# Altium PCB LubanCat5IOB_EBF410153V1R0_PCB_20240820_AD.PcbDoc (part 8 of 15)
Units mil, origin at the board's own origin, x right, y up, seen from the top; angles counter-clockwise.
Board outline 6811.02 x 4055.12 mil, 6 copper layers (TOP, GND02, ART03, ART04, PWR05, BOTTOM), stack 59.279 mil thick; 981 components, 783 nets, 3627 pads, 2669 vias.
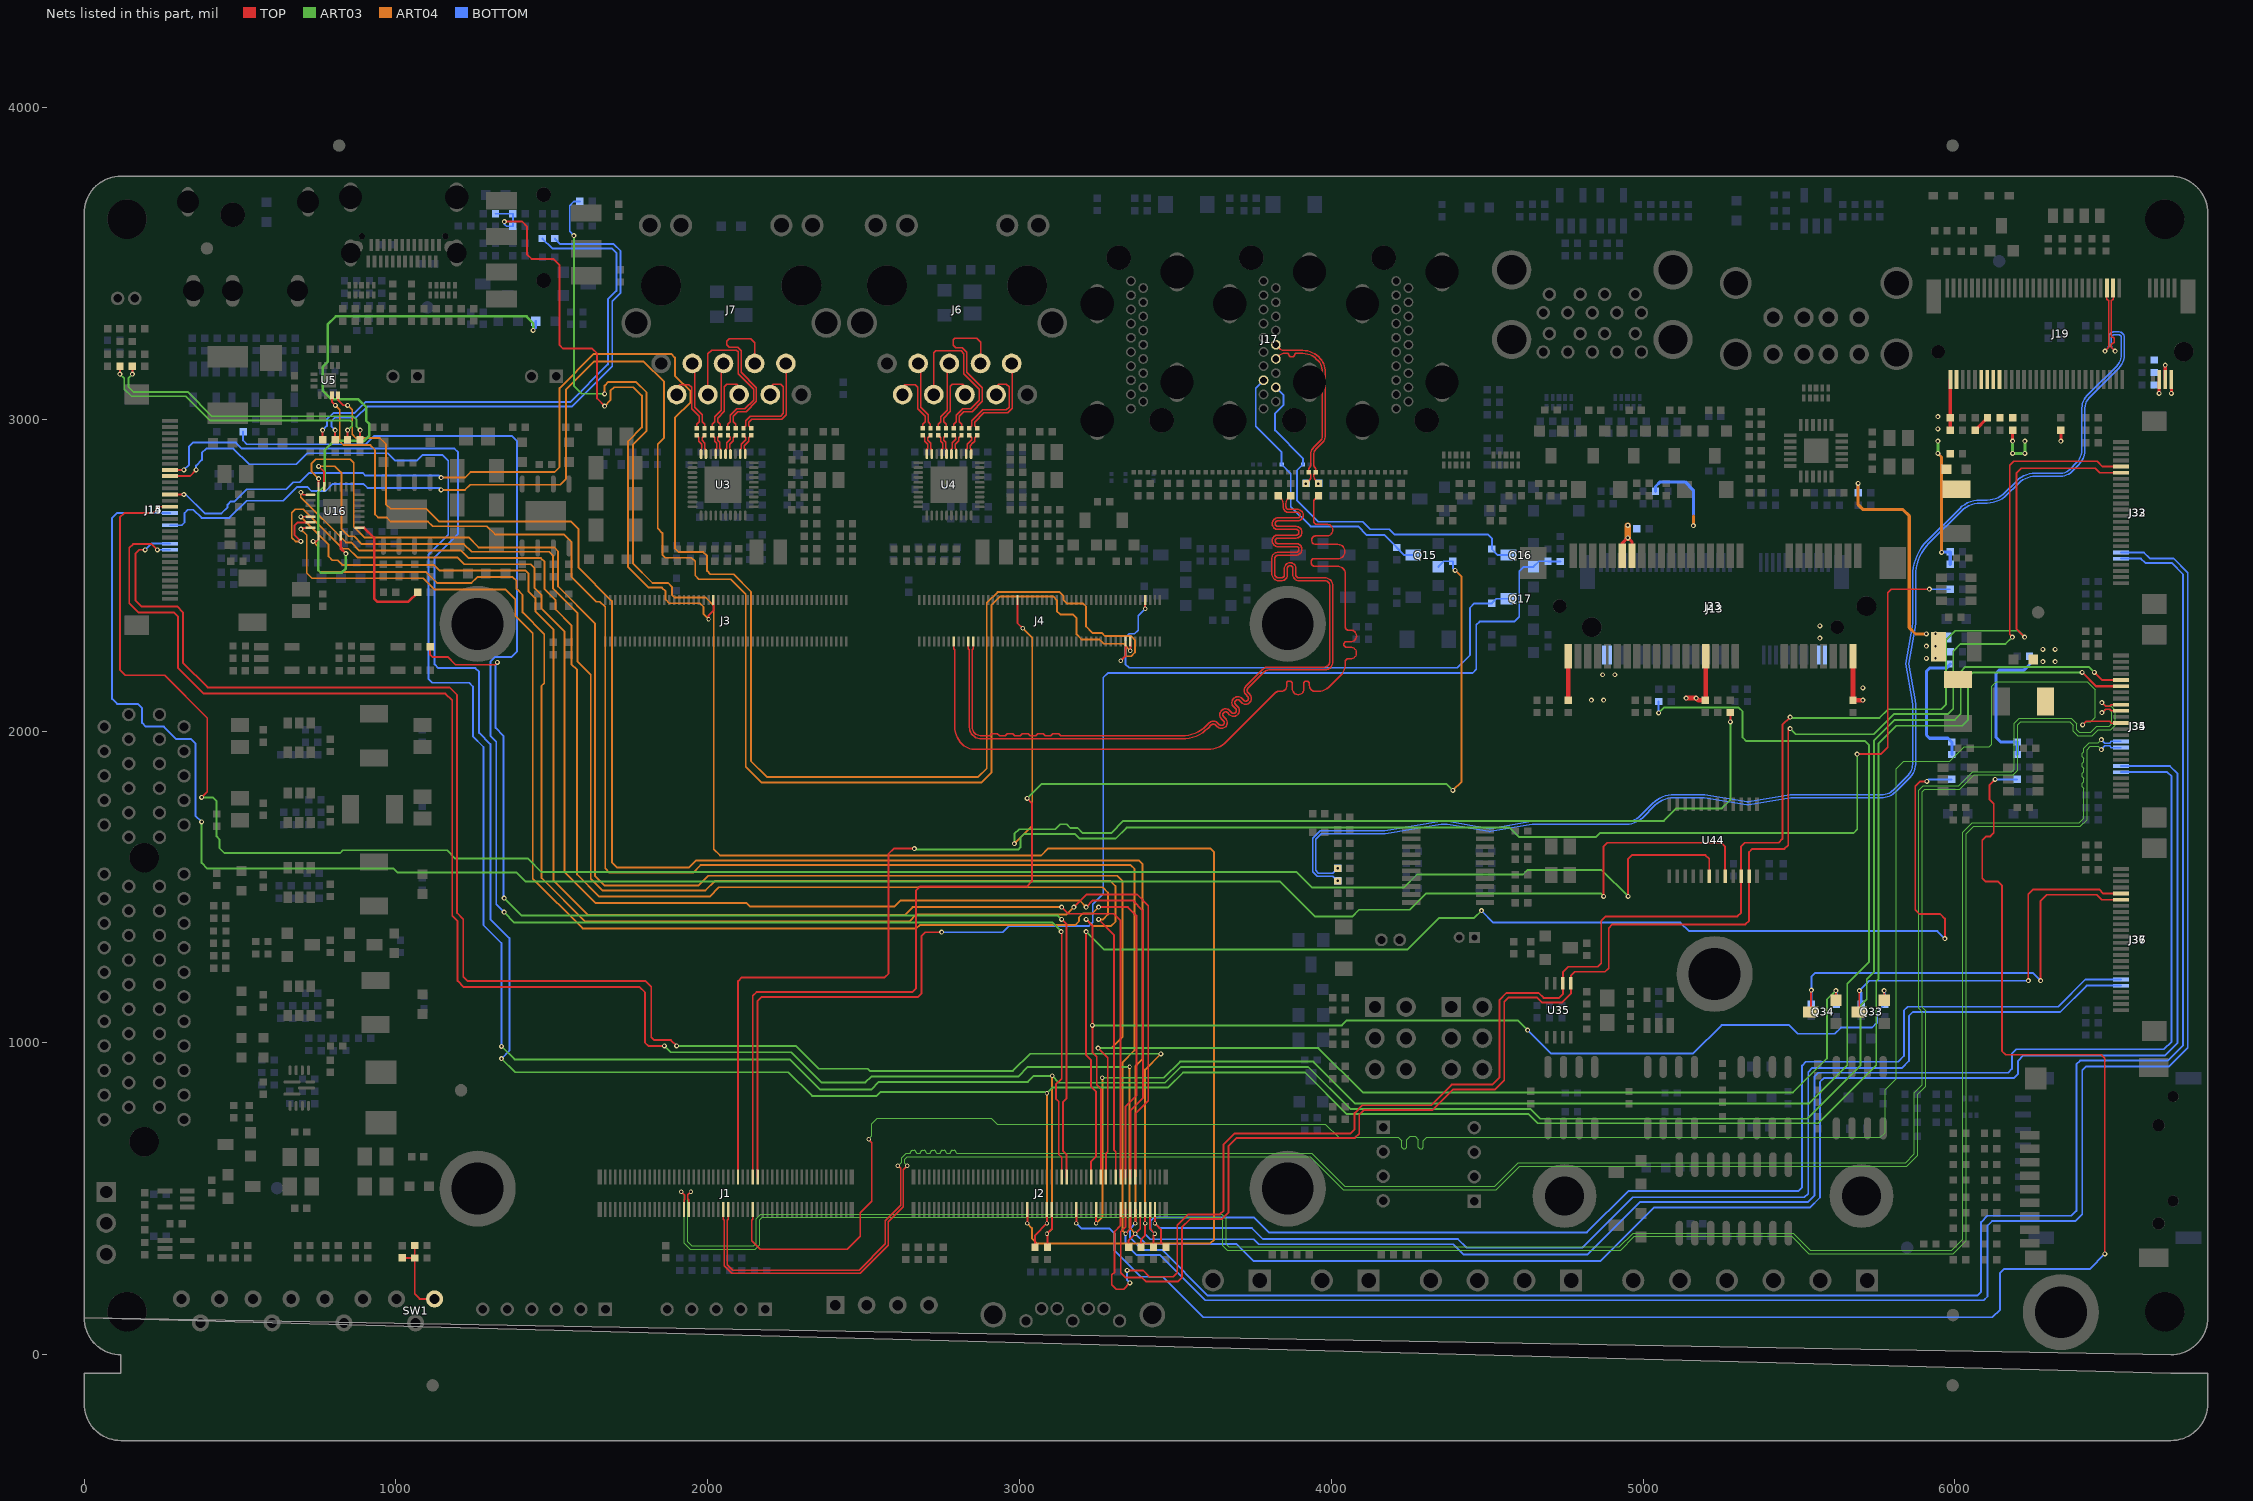
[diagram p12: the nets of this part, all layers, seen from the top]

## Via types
v1: diameter 16, hole 8, TOP to BOTTOM, 2357 vias
v2: diameter 14, hole 8, TOP to BOTTOM, 308 vias
v3: diameter 20, hole 10, TOP to BOTTOM, 4 vias

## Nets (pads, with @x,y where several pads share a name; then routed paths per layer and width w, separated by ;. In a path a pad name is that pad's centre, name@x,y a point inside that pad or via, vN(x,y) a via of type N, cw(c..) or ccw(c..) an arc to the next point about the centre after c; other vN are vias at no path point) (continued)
HDMI_TX1_D3N_PORT: C150.2 D66.2 J17.12 R182.1 | length 581.9
  TOP w4.5: J17.12@3822.28,3193.52 3833.7,3204.93 cw(c3849.61,3189.02) 3849.61,3211.52 3859.11,3211.52 cw(c3859.11,3206.26) 3864.37,3206.26 ccw(c3869.63,3206.26) 3869.63,3201 3877.11,3201 ccw(c3877.11,3206.26) 3882.37,3206.26 cw(c3887.63,3206.26) 3887.63,3211.52 3908.7,3211.52 cw(c3908.7,3149.46) 3952.59,3193.34 3958.25,3187.69 cw(c3928.67,3158.11) 3970.5,3158.11 3970.5,2942.32 cw(c3957.5,2942.32) 3966.69,2933.13 3943.76,2910.2 ccw(c3966.73,2887.23) 3934.25,2887.23 3934.25,2853.33 cw(c3924.38,2853.33) 3931.36,2846.35 3930.72,2845.71 ccw(c3937.7,2838.73) 3927.83,2838.73 D66.2@3927.83,2830 3931.73,2826.1 cw(c3923.85,2818.21) 3935,2818.21 3935,2815.99 cw(c3920.66,2815.99) 3930.8,2805.85 v1(3919,2794.05)
HDMI_TX1_D3P: C149.1 J4.15 | length 2829.7
  TOP w4.5: J4.15@2788.99,2286.88 2788.99,2263.82 2792.11,2260.7 2792.11,2015.33 ccw(c2872.84,2015.33) 2815.76,1958.25 ccw(c2854.97,1997.45) 2854.97,1942 3604.78,1942 ccw(c3604.77,2027.04) 3664.91,1966.91 3822.36,2124.36 cw(c3828.73,2118) 3828.73,2127 3838.7,2127 ccw(c3838.7,2145.5) 3857.2,2145.5 3857.2,2153.25 cw(c3864.45,2153.25) 3864.45,2160.5 3866.2,2160.5 cw(c3866.2,2151.5) 3875.2,2151.5 3875.2,2135.5 ccw(c3893.7,2135.5) 3912.2,2135.5 3912.2,2153.25 cw(c3919.45,2153.25) 3919.45,2160.5 3921.2,2160.5 cw(c3921.2,2151.5) 3930.2,2151.5 3930.2,2145.5 ccw(c3948.7,2145.5) 3948.7,2127 3958.2,2127 ccw(c3958.2,2174.79) 3992,2141 4030.69,2179.69 ccw(c3994.93,2215.45) 4045.5,2215.45 4045.5,2223.68 cw(c4053.74,2223.68) 4053.73,2231.91 4062.5,2231.91 ccw(c4062.5,2250.41) 4062.5,2268.91 4049.5,2268.91 cw(c4049.5,2277.91) 4049.5,2286.91 4063.25,2286.91 ccw(c4063.25,2304.66) 4081,2304.66 4081,2305.41 ccw(c4062.5,2305.41) 4062.5,2323.91 4054.5,2323.91 cw(c4054.5,2332.91) 4045.5,2332.91 4045.5,2503.17 ccw(c4019.67,2503.17) 4019.67,2529 3946.08,2529 cw(c3946.08,2539.08) 3936,2539.08 3936,2544 cw(c3945,2544) 3945,2553 4021.16,2553 ccw(c4021.16,2575.87) 4021.16,2598.74 3950.75,2598.74 cw(c3950.75,2612.49) 3937,2612.49 cw(c3950.75,2612.49) 3950.75,2626.24 3986.5,2626.24 ccw(c3986.5,2644.74) 3986.5,2663.24 3952.75,2663.24 cw(c3952.75,2672.24) 3943.75,2672.24 3943.75,2734.22 cw(c3956.35,2734.22) 3947.44,2743.13 C149.1@3959,2754.69
HDMI_TX1_D3P_PORT: C149.2 D67.2 J17.10 R183.1 | length 583.6
  TOP w4.5: J17.10@3822.28,3239.03 3833.76,3227.55 ccw(c3849.52,3243.32) 3849.52,3221.02 3908.7,3221.02 cw(c3908.7,3149.46) 3959.31,3200.06 3964.97,3194.41 cw(c3928.67,3158.11) 3980,3158.11 3980,2942.32 cw(c3957.5,2942.32) 3973.41,2926.41 3950.48,2903.48 ccw(c3966.73,2887.23) 3943.75,2887.23 3943.75,2853.33 ccw(c3953.62,2853.33) 3946.64,2846.35 3947.28,2845.71 cw(c3940.3,2838.73) 3950.17,2838.73 D67.2@3950.17,2830 3947.02,2826.85 ccw(c3953.09,2820.77) 3944.5,2820.77 3944.5,2815.99 ccw(c3962.46,2815.99) 3949.76,2803.29 v1(3959,2794.05)
HDMI_TX1_HPD_M0: J4.94 Q17.3 R178.2 | length 1656.1
  TOP w6: v2(3403.16,2392) J4.94@3403.16,2420.74
  BOTTOM w6: v2(3403.16,2392) 3381,2369.84 3381,2324 3369,2312 3352,2312 3340,2300 3340,2215 3352,2203 4404.63,2203 4445,2243.37 4445,2395.37 4459.32,2409.69 R178.2@4515,2409.69 4529.68,2424.37 Q17.3@4568.5,2424.37
HDMI_TX1_SBDN: C152.1 J4.23 | length 2907.9
  TOP w4.5: J4.23@2851.98,2286.88 2851.98,2263.82 2848.86,2260.7 2848.86,2011.87 ccw(c2874.69,2011.88) 2856.42,1993.6 ccw(c2878.4,2015.58) 2878.4,1984.5 2905.05,1984.5 2911.55,1991 2929.55,1991 2936.05,1984.5 2954.05,1984.5 2960.55,1991 2978.55,1991 2985.05,1984.5 3003.05,1984.5 3009.55,1991 3027.55,1991 3034.05,1984.5 3052.05,1984.5 3058.55,1991 3076.55,1991 3083.05,1984.5 3101.05,1984.5 3107.55,1991 3125.55,1991 3132.05,1984.5 3521.25,1984.5 ccw(c3521.25,2093.74) 3598.5,2016.5 3608.93,2026.93 cw(c3622.01,2013.85) 3635.09,2026.93 3641.43,2020.59 ccw(c3647.79,2026.96) 3654.16,2020.59 3654.35,2020.79 ccw(c3648.18,2026.96) 3654.35,2033.13 3647.82,2039.66 cw(c3660.91,2052.74) 3673.99,2065.82 3680.32,2059.49 ccw(c3686.69,2065.85) 3693.05,2059.49 3693.24,2059.68 ccw(c3687.07,2065.85) 3693.24,2072.03 3686.72,2078.55 cw(c3699.8,2091.64) 3712.88,2104.72 3719.22,2098.38 ccw(c3725.58,2104.74) 3731.94,2098.38 3732.14,2098.57 ccw(c3725.97,2104.75) 3732.14,2110.92 3725.61,2117.45 cw(c3738.69,2130.53) 3725.61,2143.61 3778.61,2196.61 cw(c3800.07,2175.15) 3800.07,2205.5 3978.22,2205.5 ccw(c3978.22,2222.28) 3995,2222.28 3995,2467.26 ccw(c3979.76,2467.26) 3979.76,2482.5 3895.5,2482.5 cw(c3895.5,2501) 3877,2501 3877,2521.5 ccw(c3868,2521.5) 3859,2521.5 3859,2501 cw(c3840.5,2501) 3840.5,2482.5 3831,2482.5 cw(c3831,2504.25) 3809.25,2504.25 3809.25,2553.27 cw(c3829.75,2553.27) 3829.75,2573.77 3887.5,2573.77 ccw(c3887.5,2582.77) 3887.5,2591.77 3828.75,2591.77 cw(c3828.75,2610.27) 3828.75,2628.77 3887.5,2628.77 ccw(c3887.5,2637.77) 3887.5,2646.77 3828.75,2646.77 cw(c3828.75,2665.27) 3828.75,2683.77 3891.5,2683.77 ccw(c3891.5,2692.77) 3891.5,2701.77 3863.75,2701.77 cw(c3863.75,2720.27) 3845.25,2720.27 3845.25,2731 ccw(c3824.87,2731) 3839.28,2745.41 C152.1@3830,2754.69
HDMI_TX1_SBDP: C151.1 J4.21 | length 2910.8
  TOP w4.5: J4.21@2836.23,2286.88 2836.23,2263.82 2839.36,2260.7 2839.36,2011.87 ccw(c2874.69,2011.87) 2849.71,1986.89 ccw(c2878.4,2015.58) 2878.4,1975 3521.25,1975 ccw(c3521.25,2093.74) 3605.21,2009.78 3615.65,2020.21 cw(c3622.01,2013.85) 3628.37,2020.21 ; 3628.38,2020.21 3634.71,2013.87 ccw(c3647.79,2026.96) 3660.87,2013.87 3661.07,2014.07 ccw(c3648.18,2026.96) 3661.07,2039.85 3654.54,2046.38 cw(c3660.91,2052.74) 3667.27,2059.1 3673.61,2052.77 ccw(c3686.69,2065.85) 3699.77,2052.77 3699.96,2052.96 ccw(c3687.07,2065.85) 3699.96,2078.74 3693.43,2085.27 cw(c3699.8,2091.64) 3706.16,2098 3712.5,2091.66 ccw(c3725.58,2104.74) 3738.66,2091.66 3738.86,2091.86 ccw(c3725.97,2104.75) 3738.86,2117.64 3732.33,2124.16 cw(c3738.69,2130.53) 3732.33,2136.89 3785.33,2189.89 cw(c3800.07,2175.15) 3800.07,2196 3978.22,2196 ccw(c3978.22,2222.28) 4004.5,2222.28 4004.5,2467.26 ccw(c3979.76,2467.26) 3979.76,2492 3895.5,2492 cw(c3895.5,2501) 3886.5,2501 3886.5,2521.5 ccw(c3868,2521.5) 3849.5,2521.5 3849.5,2501 cw(c3840.5,2501) 3840.5,2492 3831,2492 cw(c3831,2504.25) 3818.75,2504.25 3818.75,2553.27 cw(c3829.75,2553.27) 3829.75,2564.27 3887.5,2564.27 ccw(c3887.5,2582.77) 3887.5,2601.27 3828.75,2601.27 cw(c3828.75,2610.27) 3828.75,2619.27 3887.5,2619.27 ccw(c3887.5,2637.77) 3887.5,2656.27 3828.75,2656.27 cw(c3828.75,2665.27) 3828.75,2674.27 3891.5,2674.27 ccw(c3891.5,2692.77) 3891.5,2711.27 3863.75,2711.27 cw(c3863.75,2720.27) 3854.75,2720.27 3854.75,2731 cw(c3875.13,2731) 3860.72,2745.41 C151.1@3870,2754.69
HDMI_TX1_SCL_M0: J1.61 Q15.2 R172.2 | length 4290.1
  TOP w6: J1.61@2144.59,569.96 2144.59,1150.76 2156.59,1162.76 2656.37,1162.76 2668.37,1174.76 2668.37,1489 2680.37,1501 3023,1501 3040,1518 3040,1768.74 v1(3024.37,1784.37)
  ART03 w6: v1(3024.37,1784.37) 3070,1830 4370.37,1830 v1(4390.37,1810)
  ART04 w6: v1(4390.37,1810) 4418,1837.63 4418,2494.37 v1(4397,2515.37)
  BOTTOM w6: Q15.2@4343.5,2526.87 4361.32,2544.69 R172.2@4390,2544.69 4390,2522.37 v1(4397,2515.37)
HDMI_TX1_SCL_PORT: D36.2 J17.15 Q15.3 R173.2 | length 920
  BOTTOM w6: J17.15@3782.91,3125.16 3757.76,3100.01 3757.76,2977.24 3840.83,2894.17 D36.2@3840.83,2855 3870,2825.83 3870,2720 3933.63,2656.37 4086,2656.37 4113,2629.37 4169.68,2629.37 R173.2@4210,2589.05
  BOTTOM w6.8: R173.2@4210,2589.05 4234.68,2564.37 Q15.3@4263.5,2564.37
HDMI_TX1_SDA_M0: C154.2 J1.63 Q16.2 R175.2 | length 4440.2
  TOP w6: J1.63@2160.33,569.96 2160.33,1135.01 2172.33,1147.01 2674,1147.01 2686,1159.01 2686,1343 2698,1355 v1(2750,1355)
  BOTTOM w6: v1(2750,1355) 2947,1355 2967,1375 3223,1375 3235,1387 3235,1444 3268.85,1477.85 3268.85,2171.85 3283,2186 4453,2186 4465,2198 4465,2340.37 4476,2351.37 4587,2351.37 4603,2367.37 4603,2512.87 4617,2526.87 Q16.2@4648.5,2526.87 4666.32,2544.69 C154.2@4695,2544.69 4695.64,2544.05 R175.2@4735,2544.05
HDMI_TX1_SDA_PORT: D35.2 J17.16 Q16.3 R176.2 | length 1200.3
  BOTTOM w6: J17.16@3822.28,3102.49 3847.43,3077.34 3847.43,3046.56 3820,3019.13 3820,2964.17 3909.17,2875 D35.2@3909.17,2855 3890,2835.83 3890,2740 3958.43,2671.57 4100.8,2671.57 4125,2647.37 4185.63,2647.37 4202,2631 4502,2631 4515,2618 R176.2@4515,2584.05 4534.68,2564.37 Q16.3@4568.5,2564.37
HP_BUTTON_DET: C121.1 J3.46 R116.2 R118.1 | length 2154.1
  TOP w6: v1(1348,3634.37) 1405,3634.37 1420,3619.37 1420,3529.37 1435,3514.37 1505,3514.37 1525,3494.37 1525,3238 1536,3227 1630,3227 1645,3212 1645,3066.85 v1(1669.37,3042.48) ; v2(2002.86,2359) 2002.86,2370.86 2018.61,2386.61 J3.46@2018.61,2420.74
  ART04 w6: v1(1669.37,3042.48) 1688,3061.11 1688,3091 1700,3103 1762,3103 1789,3076 1789,2974 1745,2930 1745,2526 1811,2460 1853,2460 1865,2448 1865,2422 1877,2410 1975,2410 1987,2398 1987,2374.86 v2(2002.86,2359)
  BOTTOM w6: R116.2@1319.68,3659.37 R118.1@1375.32,3659.37 C121.1@1375.32,3619.37 1354.8,3619.37 1348,3626.17 v1(1348,3634.37)
HP_PLUG_IN_DET: J2.46 R120.2 | length 6153.1
  TOP w6: v2(3025.2,420.89) J2.46@3025.2,465.62
  ART03 w6: v1(1570.88,3589.37) 1570.88,3107.12 1596.15,3081.85 v1(1669.37,3081.85)
  ART04 w6: v1(1669.37,3081.85) 1669.37,3108 1681.37,3120 1770,3120 1804,3086 1804,2963 1760,2919 1760,2538 1823,2475 1873,2475 1885,2463 1885,2437.49 1893.49,2429 1993,2429 2019.36,2402.64 2019.36,1621.64 2040,1601 3070,1601 3093,1624 3612,1624 3624,1612 3624,369 3612,357 3056,357 3040,373 3040,406.09 v2(3025.2,420.89)
  BOTTOM w6: v1(1570.88,3589.37) 1557.72,3602.53 1557.72,3685.45 1571.32,3699.05 R120.2@1590,3699.05
I2C0_SCL_M2: J2.84 J32.6 U35.6 U44.22 | length 5994.5
  TOP w6: J2.84@3324.41,465.62 3324.41,414.42 3305,395 3305,265 3296,256 3296,223.68 3309.68,210 3334.05,210 v1(3354.05,230) ; v1(3345,270) 3397,270 3417,250 3494,250 3506,262 3506,415.21 3540.79,450 3643,450 3655,462 3655,675 3689,709 4061,709 4075,723 4075,775 4100,800 4320,800 4386,866 4516,866 4540,890 4540,1138.21 4561.79,1160 4665,1160 4681,1144 4730.8,1144 4742.8,1156 U35.6@4742.8,1191.61 4742.8,1226.8 4760,1244 4854,1244 4866,1256 4866,1392 4879.83,1405.83 5302.57,1405.83 5314.57,1417.83 U44.22@5314.57,1533.86 5314.57,1630 5326.57,1642 5435,1642 5447,1654 5447,2020 v1(5472,2045) ; v1(6223.59,2301.63) 6198,2327.22 6198,2828 6213,2843 6451,2843 6465.34,2828.66 J32.6@6533.11,2828.66
  ART03 w6: v1(5472,2045) 5475,2042 5758,2042 5786,2070 5956,2070 5972,2086 5972,2293 6001,2322 6203.22,2322 v1(6223.59,2301.63)
  BOTTOM w6: v1(3345,270) 3345,239.05 v1(3354.05,230)
I2C0_SDA_M2: J2.86 J32.5 U35.5 U44.23 | length 5851.9
  TOP w6: J2.86@3340.16,465.62 3340.16,410.16 3325,395 3325,263 3341,247 3393,247 3405,235 3509,235 3521,247 3521,409 3547,435 3649.21,435 3670,455.79 3670,668.79 3696.21,695 4076,695 4090,709 4090,768.79 4106.21,785 4324.8,785 4390.8,851 4526,851 4555,880 4555,1132 4568,1145 4660,1145 4676,1129 4739.59,1129 4768.39,1157.79 U35.5@4768.39,1191.61 4768.39,1216 4780.39,1228 4878,1228 4890,1240 4890,1368.24 4902,1380.24 5328.16,1380.24 5340.16,1392.24 U44.23@5340.16,1533.86 5340.16,1612.16 5350,1622 5453.63,1622 5465.63,1634 5465.63,2002 v1(5471.63,2008) ; v1(6184.22,2301.63) 6176,2309.85 6176,2852 6189.37,2865.37 6456.63,2865.37 6473.65,2848.35 J32.5@6533.11,2848.35
  ART03 w6: v1(5471.63,2008) 5489.63,1990 5740,1990 5805,2055 5979,2055 5995,2071 5995,2256.37 6018,2279.37 6161.96,2279.37 v1(6184.22,2301.63)
I2C1_SCL_M2: J2.88 J33.6 U5.6 | length 11265.9
  TOP w6: U5.6@794.84,3077.36 794.84,3055.79 v1(805.63,3045) ; v2(3340.16,387.89) 3355.91,403.63 J2.88@3355.91,465.62
  ART04 w6: v1(805.63,3045) 820,3030.63 820,2929 832,2917 918,2917 933,2902 933,2695 943,2685 971,2685 984,2672 1103,2672 1118,2657 1292,2657 1318,2631 1539,2631 1563,2607 1563,2495 1643,2415 1654.62,2415 1671.4,2398.21 1671.4,1559.6 1685,1546 1953,1546 1977,1570 3357,1570 3369,1558 3369,976 3331,938 3331,397.05 v2(3340.16,387.89)
  BOTTOM w6: v2(3340.16,387.89) 3340.16,354.84 3375,320 3450,320 3595.43,174.57 6092.8,174.57 6104.8,186.57 6104.8,414.17 6119.2,428.57 6386.53,428.57 6408.8,450.84 6408.8,912.57 6420.8,924.57 6687.2,924.57 6747,984.37 6747,2508.37 6701.37,2554 6625.28,2554 6606.52,2572.76 J33.6@6533.11,2572.76
I2C1_SDA_M2: J2.90 J33.5 U5.7 | length 11135.7
  TOP w6: U5.7@814.53,3077.36 814.53,3061.79 831.32,3045 v1(845,3045) ; v2(3371.66,420.89) J2.90@3371.66,465.62
  ART04 w6: v1(845,3045) 860,3030 860,2952 872,2940 949,2940 968,2921 968,2728 983,2713 1098,2713 1139,2672 1562,2672 1586,2648 1586,2524 1693,2417 1693,1579 1709,1563 1941,1563 1963,1585 3383,1585 3395,1573 3395,949 3371.66,925.66 v2(3371.66,420.89)
  BOTTOM w6: v2(3371.66,420.89) 3355,404.23 3355,375 3394,336 3457.37,336 3604,189.37 6072,189.37 6084,201.37 6084,425.37 6104,445.37 6374,445.37 6390,461.37 6390,931.37 6402,943.37 6683,943.37 6732.2,992.57 6732.2,2502.24 6695.24,2539.2 6610.8,2539.2 6596.93,2553.07 J33.5@6533.11,2553.07
I2C2_SCL_M4: J2.54 J14.9 J34.6 R360.2 | length 10359.5
  TOP w6: J14.9@275.91,2837.54 v1(320,2837.54) ; R360.2@3050,344.68 3050,382.69 v2(3088.2,420.89) J2.54@3088.19,465.62
  TOP w6.8: v1(6408.23,2188.31) 6452.6,2143.94 J34.6@6533.11,2143.94
  ART03 w6: v1(1338.74,949.74) 1382.48,906 2259,906 2335,830 2542,830 2554,842 3085.2,842 v2(3088.2,839) 3106.2,857 3477,857 3525,905 3916.7,905 4050,771.7 4633.3,771.7 4662.63,742.37 5562.37,742.37 5748,928 5748,1198 5755.3,1205.3 5755.3,1960.3 5812,2017 6024,2017 6042,2035 6042,2171.31 6059,2188.31 v1(6408.23,2188.31)
  ART04 w6: v2(3088.2,420.89) v2(3088.2,839)
  BOTTOM w6: v1(320,2837.54) 337,2854.54 337,2913 349,2925 487,2925 506,2906 1188.04,2906 1199.32,2894.72 1199.32,2633.32 1124,2558 1124,2214 1136,2202 1255,2202 1267,2190 1267,1994.13 1303,1958.13 1303,1397 1364,1336 1364,975 v1(1338.74,949.74)
I2C2_SDA_M4: J2.56 J14.10 J34.5 R361.2 | length 10371.7
  TOP w6: J14.10@275.91,2817.86 339.68,2817.86 v1(359.37,2837.54) ; R361.2@3090,344.68 3090,386.08 v2(3088.2,387.89) 3103.94,403.63 J2.56@3103.94,465.62
  TOP w6.8: v1(6447.6,2188.31) 6472.28,2163.62 J34.5@6533.11,2163.62
  ART03 w6: v1(1338.74,989.11) 1380.85,947 2264,947 2361,850 2524,850 2549,875 3027,875 3046,894 v2(3104.69,894) 3126.69,872 3466.8,872 3517.4,922.6 3926.4,922.6 4061,788 4639,788 4670.33,756.67 5526.67,756.67 5698,928 5698,1120 5717.35,1139.35 5717.35,1204.35 5741,1228 5741,1970 5807,2036 6000,2036 6019,2055 6019,2191 6034,2206 6429.91,2206 v1(6447.6,2188.31)
  ART04 w6: v2(3088.2,387.89) 3104.69,404.38 v2(3104.69,894)
  BOTTOM w6: v1(359.37,2837.54) 359.37,2851.37 378,2870 378,2892 392,2906 479,2906 529,2856 681,2856 716,2891 974,2891 997,2868 1068,2868 1085,2885 1150,2885 1168,2867 1168,2630.24 1105,2567.24 1105,2167 1117,2155 1235,2155 1247,2143 1247,1983.02 1281,1949.02 1281,1378 1338.74,1320.26 v1(1338.74,989.11)
I2C5_SCL_M3: J2.92 J15.9 J35.6 R358.2 | length 10539.4
  TOP w6: v1(235,2581.43) 216.43,2600 157,2600 145,2588 145,2410 174.99,2380.01 212.7,2380.01 289,2380 301,2368 301,2203 384,2120 1159,2120 1180.74,2098.26 1180.74,1407.26 1198,1390 1198,1199 1218,1179 1782,1179 1799,1162 1799,1001 1809.63,990.37 v1(1861.23,990.37) ; R358.2@3350,344.68 3350,366.23 v2(3371.66,387.89) 3387.41,403.63 J2.92@3387.41,465.62
  ART03 w6: v1(1861.23,990.37) 1881.6,970 2268,970 2365,873 2506,873 2525,892 2996,892 3027,923 v2(3353,923)
  ART04 w6: v2(3353,923) 3353,406.55 v2(3371.66,387.89)
  BOTTOM w6: v1(235,2581.43) J15.9@275.91,2581.43 ; v2(3371.66,387.89) 3404.55,355 3696,355 3751,300 4863,300 5034.77,471.77 5535.29,471.77 5567.6,504.08 5567.6,874.77 5579.6,886.77 6188.4,886.77 6203,901.37 6203,942.68 6220,959.68 6674.31,959.68 6714.69,1000.05 6714.69,1862.9 6689.55,1888.03 J35.6@6533.11,1888.03
I2C5_SDA_M3: J2.94 J15.10 J35.5 R359.2 | length 10517.4
  TOP w6: v1(195.63,2581.43) 176.43,2581.43 165,2570 165,2418.28 183.28,2400 298.29,2400 317,2381.28 317,2219 396,2140 1172,2140 1196,2116 1196,1417 1216,1397 1216,1212 1230,1198 1801,1198 1819,1180 1819,1018 1828,1009 1881.97,1009 v1(1900.6,990.37) ; R359.2@3390,344.68 3390,370 3403.16,383.15 v2(3403.16,420.89) J2.94@3403.16,465.62
  ART03 w6: v1(1900.6,990.37) 2282.63,990.37 2356,917 2513,917 2520,910 2979,910 3034,965 v1(3453.75,965)
  ART04 w6: v2(3403.16,420.89) 3403.16,914.16 3454,965 v1(3453.75,965)
  BOTTOM w6: v1(195.63,2581.43) 215.32,2601.12 J15.10@275.91,2601.12 ; v2(3403.16,420.89) 3403.16,386.84 3420,370 3751.37,370 3767.37,354 4392,354 4425,321 4821,321 4989.37,489.37 5528,489.37 5550,511.37 5550,892.37 5562,904.37 6171,904.37 6183,916.37 6183,965.37 6197,979.37 6670,979.37 6695,1004.37 6695,1854.75 6681.4,1868.35 J35.5@6533.11,1868.35
I2C7_SCL: J36.6 Q34.3 R331.2 | length 1437.6
  TOP w6: Q34.3@5538.5,1099.37 5538.5,1167.87 v1(5540,1169.37) ; v1(6275,1199.37) 6275,1455.77 6294.23,1475 6455,1475 6470.79,1459.21 J36.6@6533.11,1459.21
  BOTTOM w6: v1(5540,1169.37) 5540,1211.37 5552.87,1224.24 6250.13,1224.24 v1(6275,1199.37)
  BOTTOM w6.8: R331.2@5540,1124.05 v1(5540,1169.37)
I2C7_SCL_M0: J2.77 Q34.2 R332.2 U16.28 | length 7707.1
  TOP w6: U16.28@751.85,2783.74 v1(751.85,2810) ; v1(3252,983) 3283,952 3283,651 3277.17,645.17 J2.77@3277.17,569.96 ; Q34.2@5618.5,1136.87 v1(5618.5,1167.87)
  ART03 w6: v1(3252,983) 3959,983 4101,841 5481,841 5590,950 5590,1139.37 v1(5618.5,1167.87)
  ART04 w6: v1(751.85,2810) 729,2832.85 729,2858 743,2872 853,2872 865,2860 865,2655 899,2621 1233,2621 1265,2589 1508,2589 1520,2577 1520,2464 1639,2345 1639,1535 1669,1505 1971,1505 2002,1536 3314,1536 3331,1519 3331,1020 3294,983 v1(3252,983)
  BOTTOM w6.8: v1(5618.5,1167.87) 5620,1166.37 R332.2@5620,1124.05
I2C7_SDA: J36.5 Q33.3 R330.2 | length 1256.7
  TOP w6: Q33.3@5693.5,1099.37 v1(5693.5,1167.87) ; v1(6235.63,1199.37) 6235.63,1476 6252,1492.37 6462.63,1492.37 6476.1,1478.9 J36.5@6533.11,1478.9
  BOTTOM w6: v1(5693.5,1167.87) 5725,1199.37 v1(6235.63,1199.37)
  BOTTOM w6.8: v1(5693.5,1167.87) 5700,1161.37 R330.2@5700,1124.05
I2C7_SDA_M0: J2.75 Q33.2 R329.2 U16.27 | length 7698.5
  TOP w6: v1(751.85,2849.37) 769.57,2831.65 U16.27@769.57,2783.74 ; v1(3214.18,1396) 3234,1376.18 v1(3234,1056) 3234,970 3248,956 3248,866 3261.42,852.58 J2.75@3261.42,569.96 ; Q33.2@5773.5,1136.87 v1(5773.5,1167.87)
  ART03 w6: v1(3234,1056) 4034,1056 4050,1072 4598.63,1072 v1(4629.68,1040.95)
  ART04 w6: v1(751.85,2849.37) 804.63,2849.37 825,2829 825,2648.28 848.28,2625 866,2625 891,2600 1218,2600 1243,2575 1492,2575 1504,2563 1504,2457 1583,2378 1583,2223 1625,2181 1625,1526 1662,1489 1993,1489 2024,1520 3291,1520 3308,1503 3308,1389 3294,1375 3235.18,1375 v1(3214.18,1396)
  BOTTOM w6: v1(4629.68,1040.95) 4704.63,966 5161,966 5252,1057 5469,1057 5496.63,1029.37 5615,1029.37 5635,1049.37 5735,1049.37 5749.9,1064.27 5749.9,1098.95 R329.2@5775,1124.05
  BOTTOM w6.8: v1(5773.5,1167.87) 5775,1166.37 R329.2@5775,1124.05
I2C8_SCL_M2: J2.96 J37.6 R356.2 | length 3964.2
  TOP w6: J2.96@3418.9,465.62 3418.9,403.63 v2(3434.65,387.89) 3430,383.23 R356.2@3430,344.68
  BOTTOM w6: v2(3434.65,387.89) 3420,402.54 3420,428 3432,440 3751.37,440 3799.37,392 4820,392 4952.37,524.37 5498,524.37 5510,536.37 5510,927.37 5522,939.37 5818.37,939.37 5837,958 5837,1104 5849,1116 6331,1116 6418.31,1203.31 J37.6@6533.11,1203.31
I2C8_SDA_M2: J2.98 J37.5 R357.2 | length 3927.5
  TOP w6: J2.98@3434.65,465.62 v2(3434.65,420.89) 3454.5,401.04 3454.5,360.18 R357.2@3470,344.68
  BOTTOM w6: v2(3434.65,420.89) 3449.25,406.29 3745.4,406.29 3780.68,371 4406,371 4434,343 4805,343 4966.69,504.69 5517.68,504.69 5529.69,516.69 5529.69,906.09 5543.28,919.68 5830.68,919.68 5853,942 5853,1087 5865,1099 6338,1099 6422.62,1183.62 J37.5@6533.11,1183.62
I2S0_LRCK: J2.85 U16.7 | length 4706.7
  TOP w6: v1(695,2647.91) 698.94,2651.85 U16.7@726.26,2651.85 ; v1(3253.55,1435.37) 3347.63,1435.37 3375,1408 3375,831 3340.16,796.16 J2.85@3340.16,569.96
  ART04 w6: v1(695,2647.91) 714,2628.91 714,2507 731,2490 1088,2490 1124,2454 1352,2454 1383,2423 1383,2370 1439,2314 1439,1527 1599,1367 2669,1367 2680,1378 3179,1378 3191,1390 3191,1403 3203,1415 3233.18,1415 v1(3253.55,1435.37)
I2S0_MCLK: J2.81 U16.1 | length 4672.2
  TOP w6: v1(695,2766.02) 702.87,2758.15 U16.1@726.26,2758.15 ; v1(3253.55,1396) 3303,1346.55 3303,657 3308.67,651.33 J2.81@3308.67,569.96
  ART04 w6: v1(695,2766.02) 695,2750 840,2605 857,2605 883,2579 1209,2579 1233,2555 1465,2555 1477,2543 1477,2455 1512,2420 1512,2390 1563,2339 1563,2214 1581,2196 1581,1540 1652,1469 2006,1469 2036,1499 3267,1499 3284,1482 3284,1412 3268,1396 v1(3253.55,1396)
I2S0_SCLK: J2.83 U16.5 | length 4590.9
  TOP w6: v1(695,2687.28) U16.5@726.26,2687.28 ; v1(3135.44,1435.37) 3156.81,1414 3302,1414 3324.41,1391.59 J2.83@3324.41,569.96
  ART04 w6: v1(695,2687.28) 784.37,2597.91 784.37,2560 796.37,2548 814,2548 829.5,2532.5 1122.5,2532.5 1140,2515 1416,2515 1425,2506 1425,2449 1447.5,2426.5 1447.5,2384.21 1505,2326.71 1505,1522 1616,1411 2633,1411 2657.37,1435.37 v1(3135.44,1435.37)
I2S0_SDI0: J2.89 U16.8 | length 4732.6
  TOP w6: v1(734.37,2608.54) 745.85,2608.54 751.85,2614.54 U16.8@751.85,2626.26 ; v1(3174.81,1435.37) 3215.44,1476 3377,1476 3413,1440 3413,814 3371.66,772.66 J2.89@3371.66,569.96
  ART04 w6: v1(734.37,2608.54) 750,2592.91 750,2517 757,2510 1097,2510 1132,2475 1242,2475 1261,2494 1375,2494 1387,2482 1387,2456 1406.52,2436.49 1406.52,2380.49 1476,2311 1476,2154 1467,2145 1467,1529 1607,1389 2646,1389 2669,1412 3151.44,1412 v1(3174.81,1435.37)
I2S0_SDO0: J2.87 U16.6 | length 4916.6
  TOP w6: v1(695,2608.54) 675,2628.54 675,2660 684.57,2669.57 U16.6@726.26,2669.57 ; v1(3214.18,1435.37) 3235.81,1457 3363,1457 3396,1424 3396,823 3355.91,782.91 J2.87@3355.91,569.96
  ART04 w6: v1(695,2608.54) 678,2608.54 666,2620.54 666,2700 677.65,2711.65 703.35,2711.65 830,2585 848,2585 876,2557 1197,2557 1219,2535 1433,2535 1445,2523 1445,2458.72 1457,2446.72 1467.5,2436.21 1467.5,2392.5 1541,2319 1541,1548 1640,1449 2124,1449 2136,1437 2599,1437 2619,1457 3192.55,1457 v1(3214.18,1435.37)
LCD0_BL_PWM: J4.85 J14.13 | length 5637.7
  TOP w6: J14.13@275.91,2758.8 v1(320,2758.8) ; v2(3324.42,2225.14) 3340.17,2240.89 J4.85@3340.17,2286.88
  ART04 w6: v1(1145.23,2813.11) 1221.66,2813.11 1239.55,2831 1509,2831 1525,2847 1525,3100 1635,3210 1883,3210 1895,3198 1895,3140 1945,3090 1945,3055 1895,3005 1895,2586 1907,2574 1986.21,2574 1998.21,2562 1998.21,2513.79 2009,2503 2083,2503 2139,2447 2139,1904 2190,1853 2868,1853 2895,1880 2895,2411 2930,2446 3129,2446 3141,2434 3141,2421 3153,2409 3204.43,2409 3213.43,2400 3213.43,2335.57 3234,2315 3264,2315 3274,2305 3358.52,2305 3370.52,2293 3370.52,2252.09 3358.57,2240.14 3339.42,2240.14 v2(3324.42,2225.14)
  BOTTOM w6: v1(320,2758.8) 326.2,2758.8 387,2698 440.72,2698 460.48,2717.76 460.48,2726.48 470.44,2736.43 482.63,2736.43 522,2775.8 648.8,2775.8 671,2798 692,2798 722,2828 893,2828 901,2820 1138.34,2820 v1(1145.23,2813.11)
LCD0_PWR_EN: J2.59 R306.1 | length 5140.9
  TOP w6: v1(3134,1357) 3135.44,1355.56 3135.44,885 3117,866.56 3117,821 3126,812 3126,642 3135.44,632.56 J2.59@3135.44,569.96
  ART03 w6: v1(1347,1419) 1380,1386 3106.07,1386 3134,1358.07 v1(3134,1357)
  BOTTOM w6: R306.1@510,2960.32 510,2932 522,2920 903,2920 929.96,2946.96 1372.04,2946.96 1388,2931 1388,2255 1371,2238 1318,2238 1304,2224 1304,1984 1322,1966 1322,1444 v1(1347,1419)
LCD0_RST: J14.15 U44.18 | length 6559.9
  TOP w6: J14.15@275.91,2719.43 239.67,2719.43 219.61,2699.37 129,2699.37 115,2685.37 115,2196 132,2179 258,2179 395,2042 395,1805.47 v1(377.01,1787.48) ; v1(4952.05,1469.77) 4952.05,1590 4964.05,1602 5200.2,1602 5212.2,1590 U44.18@5212.2,1533.86
  ART03 w6: v1(377.01,1787.48) 412.4,1787.48 425,1774.88 425,1661.97 434,1652.97 434,1625 450,1609 821,1609 830,1618 1164,1618 1191,1591 1424,1591 1467,1548 3889,1548 3939,1498 4233,1498 4275,1540 4615,1540 4629.37,1554.37 4867.45,1554.37 v1(4952.05,1469.77)
LCD1_BL_PWM: J4.87 J15.13 | length 5499.1
  TOP w6: v2(3355.92,2258.14) J4.87@3355.92,2286.88
  ART04 w6: v1(1145.23,2773.74) 1221.66,2773.74 1237.92,2790 1527,2790 1546,2809 1546,3096 1635,3185 1795,3185 1860,3120 1860,2940.2 1840,2920.2 1840,2650 1855,2635 1855,2565 1864,2556 1948,2556 1960,2544 1960,2499 1972,2487 2074.03,2487 2122,2439.03 2122,1886 2173,1835 2878,1835 2910.56,1867.56 2910.56,2404.56 2938,2432 3108,2432 3120,2420 3120,2385 3131,2374 3171,2374 3183,2362 3183,2310 3199,2294 3256,2294 3270,2280 3334.06,2280 v2(3355.92,2258.14)
  BOTTOM w6: J15.13@275.91,2660.17 313.17,2660.17 322,2669 322,2699 333,2710 350.82,2710 376.82,2684 466.09,2684 521,2738.91 638.91,2738.91 683.02,2783.02 715.98,2783.02 729,2770 775,2770 798,2793 896,2793 909,2780 1138.97,2780 v1(1145.23,2773.74)
LCD1_PWR_EN: J2.61 R305.1 | length 3685.1
  TOP w6: R305.1@1109.68,2270 1109.68,2245.32 1117.21,2237.79 1166.21,2237.79 1191.24,2212.76 1318.39,2212.76 v1(1325.63,2220) ; v1(3135.44,1396) 3151.19,1380.25 3151.19,822.19 3140,811 3140,653 3151.19,641.81 J2.61@3151.19,569.96
  ART03 w6: v1(1347,1464) 1403,1408 3123.44,1408 v1(3135.44,1396)
  BOTTOM w6: v1(1325.63,2220) 1320,2214.37 1320,2010 1345,1985 1345,1466 v1(1347,1464)
LCD1_RST: J15.15 U44.20 | length 6777.1
  TOP w6: v1(4873.31,1469.77) 4873.31,1630 4885.31,1642 5251,1642 5263.39,1629.61 U44.20@5263.39,1533.86
  ART03 w6: v1(377.01,1708.74) 377.01,1576.99 395,1559 993,1559 1006,1546 1387,1546 1416,1517 3836,1517 3948,1405 4067,1405 4089,1427 4252,1427 4304.37,1479.37 4863.71,1479.37 v1(4873.31,1469.77)
  BOTTOM w6: J15.15@275.91,2699.54 275.74,2699.37 105,2699.37 90,2684.37 90,2103.37 106,2087.37 172,2087.37 186,2073.37 186,2026.37 198,2014.37 256,2014.37 296,1974.37 343,1974.37 357,1960.37 357,1728.75 v1(377.01,1708.74)
LOUT1: C122.1 U16.12 | length 1973.9
  TOP w8: U16.12@822.72,2626.26 822.72,2585.82 v1(839.37,2569.17)
  ART03 w8: v1(839.37,2569.17) 839.37,2521.37 826,2508 759,2508 751,2516 751,2766 772,2787 772,2901 802,2931 898,2931 914,2947 914,2986 905,2995 905,3039 880,3064 793,3064 766,3091 766,3169 781,3184 781,3304 807,3330 1419,3330 1440.37,3308.63 v1(1440.37,3285.37)
  BOTTOM w8: v1(1440.37,3285.37) 1448.5,3293.5 C122.1@1448.5,3314.37
LOUT2: C279.1 U16.15 | length 411.3
  TOP w8: U16.15@883.74,2651.85 898.15,2651.85 930,2620 930,2425 940,2415 1040.32,2415 C279.1@1070.32,2445
M2EKEY_3V3: C128.2 C129.1 C130.1 J13.2 J13.4 J13.72 J13.74 L25.2 R138.2 R147.1 | length 738.9
  ART04 w10: v1(5161.42,2659) 5161.42,2688.95
  BOTTOM w10: R147.1@5040,2769.05 5040,2784.37 5055,2799.37 5135,2799.37 5161.42,2772.95 v1(5161.42,2659) ; R138.2@6200.32,1925 C128.2@6200.32,1965 6147,1965 6132,1980 6132,2185 6142,2195 6220.63,2195 6241,2215.37
  other v1: 4870.08,2180.71 4909.45,2180.71 6282.33,2222.89 6321.7,2222.89 6282.33,2262.26 6321.7,2262.26 5567.06,2298.31 5567.06,2337.68
M2EKEY_NWDISABLE: J2.74 R146.2 | length 4910.3
  TOP w6: v2(3245.68,420.89) J2.74@3245.67,465.62
  ART03 w6: v2(3266,888) 3463,888 3515,940 3942.65,940 4077.65,805 5531.84,805 5654.85,928.01 5654.85,1189.22 5724.32,1258.69 5724.32,1956 5712.32,1968 5331,1968 5319,1980 5319,2063.37 5307,2075.37 5067,2075.37 v1(5050,2058.37)
  ART04 w6: v2(3245.68,420.89) 3266,441.21 v2(3266,888)
  BOTTOM w6: v1(5050,2058.37) R146.2@5050,2094.69
M2EKEY_PWR_EN: J2.66 R140.2 | length 5646.7
  TOP w6: v2(3182.68,420.89) J2.66@3182.68,465.62 ; v1(6128.97,1845) 6111.57,1827.6 6111.57,1780.52 6124.88,1767.21 6124.88,1673.25 6114,1662.37 6101,1662.37 6088,1649.37 6088,1528 6099,1517 6139,1517 6151,1505 6151,974 6163,962 6469,962 6481,950 v1(6481,323.37)
  BOTTOM w6: v2(3182.68,420.89) 3198.57,405 3288,405 3305,388 3305,334.04 3389.04,250 3460,250 3590,120 6120.63,120 6145,144.37 6145,262.37 6157,274.37 6432,274.37 v1(6481,323.37) ; v1(6128.97,1845) R140.2@6200.32,1845
M2PCIE_3V3: C157.2 C158.1 C159.1 C169.1 C170.1 C171.1 C172.1 C173.1 C174.1 C181.1 C182.1 C183.1 J19.2 J19.4 J19.12 J19.14 J19.16 J19.18 J19.70 J19.72 J19.74 L16.2 R218.2 R236.2 R237.2 | length 974.9
  TOP w10: C171.1@5985.32,2965 C170.1@5985.32,3005 5985.32,3127.76 J19.2@5985.91,3128.35 ; R236.2@6065,2965.32 6065.64,2965.32 C182.1@6105,3004.68 ; v1(6185.32,2930) C181.1@6185.32,2965 ; v1(6340,2930.32) R237.2@6340,2965.32 ; v1(6655.2,3082.84) J19.70@6655.2,3128.35 ; J19.72@6674.89,3128.35 v1(6674.89,3173.86) ; v1(6694.57,3082.84) J19.74@6694.57,3128.35
  ART03 w10: v1(5945.95,2890.63) v1(5945.95,2930) ; v1(6185.32,2930) v1(6185.32,2890.63) v1(6224.69,2890.63) v1(6224.68,2930)
  ART04 w10: v1(5945.95,2890.63) 5957.37,2879.21 v1(5957.37,2573.11)
  BOTTOM w10: v1(5957.37,2573.11) 5959.26,2575 C157.2@5985.32,2575 R218.2@5985.32,2535
  other v1: 5945.95,2969.37 5945.95,3008.74
M2PCIE_PWR_EN: J1.55 R221.2 | length 5751.9
  TOP w6: J1.55@2097.34,569.96 2097.34,1198 2109.34,1210 2568,1210 2580,1222 2580,1606 2597,1623 v1(2663,1623) ; v1(5687,1926) 5763,1926 5785,1948 5785,2444.37 5795.63,2455 v1(5918,2455)
  ART03 w6: v1(2663,1623) 2666,1620 2996,1620 3003,1627 3003,1658 3015,1670 3178,1670 3193,1655 3308,1655 3343.51,1690.51 4572.49,1690.51 4603,1660 4848,1660 4861,1673 5675,1673 5687,1685 v1(5687,1926)
  BOTTOM w6: v1(5918,2455) R221.2@5985.32,2455
M2PCIE_REF_CLKN: J19.53 R229.2 R231.1 | length 4289.2
  TOP w4.5: v1(6481.64,3219) 6492.97,3230.33 6492.97,3380.12 6487.88,3385.2 J19.53@6487.88,3421.65
  BOTTOM w4.5: v1(4020.32,1559.37) 4005.07,1544.12 3959,1544.12 3950,1553.12 3950,1652.57 3967.93,1670.5 4165.82,1670.5 cw(c4165.81,1661.49) 4166.57,1670.46 cw(c4165.83,1661.49) 4167.32,1670.37 ; 4167.36,1670.36 ccw(c4170.52,1688.59) 4173.69,1670.36 4352.24,1701.37 cw(c4353.78,1692.5) 4353.78,1701.5 4369.84,1701.5 cw(c4369.83,1692.5) 4371.37,1701.37 ; 4371.38,1701.37 4505.14,1678.14 ccw(c4508.31,1696.37) 4511.47,1678.14 4645.24,1701.37 cw(c4646.78,1692.5) 4646.78,1701.5 4948,1701.5 ccw(c4948,1773.77) 4999.1,1722.67 5038.22,1761.78 cw(c5099.1,1700.91) 5099.1,1787 5195.12,1787 cw(c5195.12,1778) 5196.66,1786.87 5332.28,1763.32 ccw(c5335.45,1781.55) 5338.61,1763.32 5474.24,1786.87 cw(c5475.78,1778) 5475.78,1787 5771,1787 ccw(c5771,1836.8) 5806.22,1801.59 5806.82,1802.19 5856.81,1852.18 ccw(c5815.32,1893.67) 5874,1893.67 ; 5874,1893.67 5874,2083.75 5872.76,2098.17 5852.35,2215.75 5872.76,2333.32 5874,2347.75 5874,2498.19 cw(c6020.8,2498.19) 5917,2602 6021.88,2706.88 cw(c6081,2647.77) 6081,2731.37 6104,2731.37 ccw(c6104,2820.7) 6167.16,2757.53 6201.81,2792.18 6205.3,2795.67 cw(c6258,2742.97) 6258,2817.5 6339.32,2817.5 ccw(c6339.32,2869.68) 6376.22,2832.78 6396.89,2853.46 ccw(c6348.35,2902) 6417,2902 6417,3036 cw(c6462.87,3036) 6430.43,3068.43 6440,3078 6525.47,3163.47 ccw(c6481.94,3207) 6543.5,3207 6543.5,3262 ccw(c6525,3262) 6525,3280.5 6511.47,3280.5 ccw(c6511.47,3262) 6492.97,3262 6492.97,3234.06 cw(c6483.97,3234.06) 6490.33,3227.69 v1(6481.64,3219)
M2PCIE_REF_CLKP: J19.55 R228.2 R232.1 | length 4286.8
  TOP w4.5: J19.55@6507.56,3421.65 6507.56,3385.21 6502.47,3380.12 6502.47,3267.36 ccw(c6507.23,3267.36) 6507.23,3262.59 cw(c6507.24,3257.83) 6512,3257.83 6512,3249.36 cw(c6507.24,3249.36) 6507.24,3244.59 ccw(c6507.23,3239.83) 6502.47,3239.83 6502.47,3230.33 v1(6513.8,3219)
  BOTTOM w4.5: v1(4020.32,1519.37) 4005.07,1534.62 3955.06,1534.62 3940.5,1549.18 3940.5,1656.5 3964,1680 4165.82,1680 cw(c4165.82,1661.49) 4168.89,1679.74 ccw(c4170.52,1688.59) 4172.06,1679.72 4350.61,1710.73 cw(c4353.78,1692.5) 4353.78,1711 4369.84,1711 cw(c4369.84,1692.5) 4373,1710.73 4506.77,1687.5 ccw(c4508.31,1696.37) 4509.85,1687.5 4643.61,1710.73 cw(c4646.78,1692.5) 4646.78,1711 4948,1711 ccw(c4948,1773.77) 4992.39,1729.38 5031.5,1768.5 cw(c5099.1,1700.91) 5099.1,1796.5 5195.12,1796.5 cw(c5195.12,1778) 5198.29,1796.23 5333.91,1772.68 ccw(c5335.45,1781.55) 5336.99,1772.68 5472.61,1796.23 cw(c5475.78,1778) 5475.78,1796.5 5771,1796.5 ccw(c5771,1836.8) 5799.5,1808.3 5800.1,1808.9 5850.1,1858.9 ccw(c5815.32,1893.67) 5864.5,1893.67 5864.5,2083.34 5863.33,2096.95 5842.7,2215.75 5863.33,2334.55 5864.5,2348.16 5864.5,2498.19 cw(c6020.8,2498.2) 5910.28,2608.71 6015.16,2713.6 cw(c6081,2647.76) 6081,2740.87 6104,2740.87 ccw(c6104,2820.7) 6160.45,2764.25 6195.09,2798.9 6198.58,2802.39 cw(c6258,2742.97) 6258,2827 6339.32,2827 ccw(c6339.32,2869.68) 6369.5,2839.5 6390.18,2860.18 ccw(c6348.35,2902) 6407.5,2902 6407.5,3036 cw(c6462.87,3036) 6423.72,3075.15 6433.28,3084.72 6518.75,3170.18 ccw(c6481.94,3207) 6534,3207 6534,3262 ccw(c6525,3262) 6525,3271 6511.47,3271 ccw(c6511.47,3262) 6502.47,3262 6502.47,3234.06 ccw(c6511.47,3234.06) 6505.11,3227.7 v1(6513.8,3219)
MASKROM: C4.1 D2.2 R1.1 SW1.2 | length 266.2
  TOP w6: R1.1@1020,310.32 1020.32,310 D2.2@1060.32,310 ; C4.1@1060.32,350 D2.2@1060.32,310 ; SW1.2@1124.14,178.81 1076.18,178.81 1060.32,194.68 D2.2@1060.32,310
MDIN0_PHY0: R366.1 U4.2 | length 71.5
  TOP w4.5: U4.2@2829.12,2888.43 2829.12,2903.71 2832.41,2907 2832.41,2919.44 2846.97,2934 2847.16,2934 2847.16,2941.42 R366.1@2839.41,2949.17
MDIN0_PHY0_RJ45: J6.3 R366.2 | length 305.5
  TOP w4.5: R366.2@2839.41,2970.83 2847.16,2978.58 2847.16,2995.24 2881.91,3030 2958.41,3030 2967.41,3039 2967.41,3104 2958.41,3113 2934.2,3113 2925.2,3104 J6.3@2925.2,3079.14
MDIN0_PHY1: R374.1 U3.2 | length 71.5
  TOP w4.5: U3.2@2104.71,2888.43 2104.71,2903.71 2108,2907 2108,2919.44 2122.56,2934 2122.75,2934 2122.75,2941.42 R374.1@2115,2949.17
MDIN0_PHY1_RJ45: J7.3 R374.2 | length 317.4
  TOP w4.5: R374.2@2115,2970.83 2122.75,2978.58 2122.75,2995.24 2137.31,3009.81 2234,3009.81 2243,3018.81 2243,3104 2234,3113 2209.79,3113 2200.79,3104 J7.3@2200.79,3079.14
MDIN1_PHY0: R368.1 U4.5 | length 69.7
  TOP w4.5: U4.5@2781.87,2888.43 2781.87,2904.46 2784.99,2907.59 2784.99,2924.02 2796.41,2935.44 2796.41,2942.17 R368.1@2789.41,2949.17
MDIN1_PHY0_RJ45: J6.7 R368.2 | length 547.2
  TOP w4.5: J6.7@2725.2,3079.14 2725.2,3213 2732.2,3220 2812.57,3220 2821.91,3210.66 2821.91,3146.5 2871.41,3097 2871.41,3061.44 2843.97,3034 2817.41,3034 2797.16,3013.75 2797.16,2991.4 2789.41,2983.65 R368.2@2789.41,2970.83
MDIN1_PHY1: R376.1 U3.5 | length 69.7
  TOP w4.5: U3.5@2057.46,2888.43 2057.46,2904.46 2060.59,2907.59 2060.59,2924.02 2072,2935.44 2072,2942.17 R376.1@2065,2949.17
MDIN1_PHY1_RJ45: J7.7 R376.2 | length 549.8
  TOP w4.5: J7.7@2000.79,3079.14 2000.79,3210 2012.29,3221.5 2092.06,3221.5 2097.5,3216.06 2097.5,3146.5 2147,3097 2147,3061.44 2119.56,3034 2093,3034 2072.75,3013.75 2072.75,2991.4 2065,2983.65 R376.2@2065,2970.83
MDIN2_PHY0: R370.1 U4.7 | length 67.9
  TOP w4.5: R370.1@2739.41,2949.17 2747.41,2941.17 2747.41,2929 2753.51,2922.9 2753.51,2907.1 2750.38,2903.97 U4.7@2750.38,2888.43
MDIN2_PHY0_RJ45: J6.6 R370.2 | length 223.1
  TOP w4.5: R370.2@2739.41,2970.83 2739.41,2983.65 2747.16,2991.4 2747.16,3008.07 2768.41,3029.32 2768.41,3172.35 J6.6@2775.2,3179.14
MDIN2_PHY1: R378.1 U3.7 | length 67.9
  TOP w4.5: R378.1@2015,2949.17 2023,2941.17 2023,2929 2029.1,2922.9 2029.1,2907.1 2025.97,2903.97 U3.7@2025.97,2888.43
MDIN2_PHY1_RJ45: J7.6 R378.2 | length 223.1
  TOP w4.5: R378.2@2015,2970.83 2015,2983.65 2022.75,2991.4 2022.75,3008.07 2044,3029.32 2044,3172.35 J7.6@2050.79,3179.14
MDIN3_PHY0: R372.1 U4.10 | length 68.4
  TOP w4.5: R372.1@2689.41,2949.17 2696.41,2942.17 2696.41,2929 2705.55,2919.86 2705.55,2907.14 2703.13,2904.72 U4.10@2703.13,2888.43
MDIN3_PHY0_RJ45: J6.9 R372.2 | length 224.5
  TOP w4.5: J6.9@2625.2,3079.14 2625.2,3103.5 2632.7,3111 2665.91,3111 2673.41,3103.5 2673.41,3034 2697.16,3010.25 2697.16,2991.4 2689.41,2983.65 R372.2@2689.41,2970.83
MDIN3_PHY1: R380.1 U3.10 | length 68.4
  TOP w4.5: R380.1@1965,2949.17 1972,2942.17 1972,2929 1981.14,2919.86 1981.14,2907.14 1978.72,2904.72 U3.10@1978.72,2888.43
MDIN3_PHY1_RJ45: J7.9 R380.2 | length 222.7
  TOP w4.5: J7.9@1900.79,3079.14 1900.79,3102 1909.79,3111 1940,3111 1949,3102 1949,3034 1972.75,3010.25 1972.75,2991.4 1965,2983.65 R380.2@1965,2970.83
MDIP0_PHY0: R365.1 U4.1 | length 71.4
  TOP w4.5: U4.1@2844.87,2888.43 2844.87,2904.54 2841.91,2907.5 2841.91,2915.5 2850.91,2924.5 2851.09,2924.5 2856.66,2930.06 2856.66,2941.42 R365.1@2864.41,2949.17
MDIP0_PHY0_RJ45: J6.2 R365.2 | length 306.8
  TOP w4.5: R365.2@2864.41,2970.83 2856.66,2978.58 2856.66,2991.31 2885.85,3020.5 2962.34,3020.5 2976.91,3035.06 2976.91,3177.43 J6.2@2975.2,3179.14
MDIP0_PHY1: R373.1 U3.1 | length 71.4
  TOP w4.5: U3.1@2120.46,2888.43 2120.46,2904.54 2117.5,2907.5 2117.5,2915.5 2126.5,2924.5 2126.69,2924.5 2132.25,2930.06 2132.25,2941.42 R373.1@2140,2949.17
MDIP0_PHY1_RJ45: J7.2 R373.2 | length 318.7
  TOP w4.5: R373.2@2140,2970.83 2132.25,2978.58 2132.25,2991.31 2141.25,3000.31 2237.94,3000.31 2252.5,3014.87 2252.5,3177.43 J7.2@2250.79,3179.14
MDIP1_PHY0: R367.1 U4.4 | length 70.3
  TOP w4.5: U4.4@2797.62,2888.43 2797.62,2903.79 2794.49,2906.91 2794.49,2920.09 2805.91,2931.5 2805.91,2940.67 R367.1@2814.41,2949.17
MDIP1_PHY0_RJ45: J6.4 R367.2 | length 547.5
  TOP w4.5: R367.2@2814.41,2970.83 2814.41,2983.65 2806.66,2991.4 2806.66,3009.81 2821.34,3024.5 2847.91,3024.5 2880.91,3057.5 2880.91,3100.94 2831.41,3150.44 2831.41,3214.59 2816.5,3229.5 2795.5,3229.5 2788,3237 2788,3255 2793,3260 2863,3260 2875.2,3247.8 J6.4@2875.2,3179.14
MDIP1_PHY1: R375.1 U3.4 | length 70.3
  TOP w4.5: U3.4@2073.21,2888.43 2073.21,2903.79 2070.09,2906.91 2070.09,2920.09 2081.5,2931.5 2081.5,2940.67 R375.1@2090,2949.17
MDIP1_PHY1_RJ45: J7.4 R375.2 | length 549.8
  TOP w4.5: R375.2@2090,2970.83 2090,2983.65 2082.25,2991.4 2082.25,3009.81 2096.94,3024.5 2123.5,3024.5 2156.5,3057.5 2156.5,3100.94 2107,3150.44 2107,3220 2096,3231 2069.5,3231 2061,3239.5 2061,3250.5 2069.5,3259 2137.79,3259 2150.79,3246 J7.4@2150.79,3179.14
MDIP2_PHY0: R369.1 U4.6 | length 67.7
  TOP w4.5: R369.1@2764.41,2949.17 2756.91,2941.67 2756.91,2932.94 2763.01,2926.84 2763.01,2907.4 2766.13,2904.28 U4.6@2766.13,2888.43
MDIP2_PHY0_RJ45: J6.5 R369.2 | length 225.7
  TOP w4.5: R369.2@2764.41,2970.83 2764.41,2983.65 2756.66,2991.4 2756.66,3004.13 2777.91,3025.38 2777.91,3105.5 2784.41,3112 2818.7,3112 2825.2,3105.5 J6.5@2825.2,3079.14
MDIP2_PHY1: R377.1 U3.6 | length 67.7
  TOP w4.5: R377.1@2040,2949.17 2032.5,2941.67 2032.5,2932.94 2038.6,2926.84 2038.6,2907.4 2041.72,2904.28 U3.6@2041.72,2888.43
MDIP2_PHY1_RJ45: J7.5 R377.2 | length 224.5
  TOP w4.5: R377.2@2040,2970.83 2040,2983.65 2032.25,2991.4 2032.25,3004.13 2053.5,3025.38 2053.5,3104.5 2061,3112 2093.29,3112 2100.79,3104.5 J7.5@2100.79,3079.14
MDIP3_PHY0: R371.1 U4.9 | length 69.2
  TOP w4.5: R371.1@2714.41,2949.17 2706.41,2941.17 2706.41,2932.44 2715.05,2923.8 2715.05,2906.36 2718.88,2902.53 U4.9@2718.88,2888.43
MDIP3_PHY0_RJ45: J6.8 R371.2 | length 224.5
  TOP w4.5: J6.8@2675.2,3179.14 2682.91,3171.43 2682.91,3037.94 2706.66,3014.19 2706.66,2991.4 2714.41,2983.65 R371.2@2714.41,2970.83
MDIP3_PHY1: R379.1 U3.9 | length 69.2
  TOP w4.5: R379.1@1990,2949.17 1982,2941.17 1982,2932.44 1990.64,2923.8 1990.64,2906.36 1994.47,2902.53 U3.9@1994.47,2888.43
MDIP3_PHY1_RJ45: J7.8 R379.2 | length 224.5
  TOP w4.5: J7.8@1950.79,3179.14 1958.5,3171.43 1958.5,3037.94 1982.25,3014.19 1982.25,2991.4 1990,2983.65 R379.2@1990,2970.83
MIC1N: C113.2 R117.2 | length 1647.2
  TOP w6: C113.2@805,2934.05 v1(805,2965)
  BOTTOM w6: v1(805,2965) 793,2977 793,2993.97 805,3005.97 872.77,3005.97 907.8,3041 1564.8,3041 1694,3170.2 1694,3379.2 1721,3406.2 1721,3539.8 1698.8,3562 1527.69,3562 R117.2@1510,3579.69
MIC1P: C112.2 R114.2 | length 1670.6
  TOP w6: C112.2@765,2934.05 v1(765,2965)
  BOTTOM w6: v1(765,2965) 779,2979 779,2999.77 799.2,3019.97 866.97,3019.97 902,3055 1559,3055 1680,3176 1680,3385 1707,3412 1707,3534 1693,3548 1501.69,3548 R114.2@1470,3579.69
MIC2N: C117.2 R134.2 | length 914.8
  TOP w6: v1(155,3145) R134.2@155,3169.69 ; C117.2@885,2934.05 v1(885,2965)
  ART03 w6: v1(155,3145) 143,3133 143,3102.8 157.8,3088 331.83,3088 409.86,3009.97 862.03,3009.97 874,2998 874,2976 v1(885,2965)
MIC2P: C115.2 R130.2 | length 916
  TOP w6: v1(115,3145) R130.2@115,3169.69 ; C115.2@845,2934.05 v1(845,2965)
  ART03 w6: v1(115,3145) 129,3131 129,3097 152,3074 326.03,3074 404.06,2995.97 854,2995.97 860,2989.97 860,2980 v1(845,2965)
MINIPCIE_3V3: C200.1 C201.1 C202.1 C203.1 C220.1 C221.1 C222.1 C223.1 C315.1 J23.2 J23.24 J23.39 J23.41 J23.52 L18.2 R254.1 R264.1 | length 1806.6
  TOP w10: J23.41@4933.07,2562.26 4933.07,2602.44 4950.26,2619.63 v1(4951,2619.63) 4951.74,2619.63 4964.57,2606.8 J23.39@4964.57,2562.26
  TOP w15: J23.52@4759.84,2239.43 4760,2239.27 C220.1@4760,2099.05 ; v1(5138.51,2106) v1(5170,2106) 5176.95,2099.05 C221.1@5200,2099.05 5200.79,2099.84 J23.24@5200.79,2239.43 ; J23.2@5673.23,2239.43 C223.1@5673.23,2099.05 v1(5705,2099.05)
  ART04 w10: v1(5690,2794.37) 5690,2726.37 5706,2710.37 5834,2710.37 5854,2690.37 5854,2331.63 5874,2311.63 v1(5908.63,2311.63)
  ART04 w20: v1(4951,2619.63) v1(4951,2659.74)
  BOTTOM w10: R264.1@5690,2764.05 v1(5690,2794.37) ; C203.1@5985.32,2215 5972.32,2202 5919,2202 5909,2192 5909,1987 5919,1977 5978.32,1977 C200.1@5990.32,1965 R254.1@5990.32,1925
  other v1: 4834.05,2099.06 4873.42,2099.06 5705,2138.42 5908.63,2232.89 5938,2232.89 5908.63,2272.26 5938,2272.26 5938,2311.63
MINIPCIE_NWDISABLE: J4.42 R267.2 | length 3501.8
  TOP w6: J4.42@2993.71,2420.74 2993.71,2346.29 v2(3010,2330) ; v1(5280,2029.37) R267.2@5280,2059.69
  ART03 w6: v1(2983.63,1639) 2983.63,1670 2998.63,1685 3115,1685 3131.33,1701.33 3151.21,1701.33 3163.37,1689.17 3186.21,1689.17 3202.38,1673 3294,1673 3333,1712 5067,1712 5107,1752 5253,1752 5280,1779 v1(5280,2029.37)
  ART04 w6: v1(2983.63,1639) 3041,1696.37 3041,2299 v2(3010,2330)
MINIPCIE_PWR_EN: J2.71 R262.1 | length 4365.4
  TOP w6: v1(3214.18,1356.63) 3214,1356.45 3214,961 3229,946 3229,861 3245,845 3245,634.67 3229.93,619.6 J2.71@3229.93,569.96 ; v1(5910.63,1838.74) 5888.37,1838.74 5873,1823.37 5873,1426.97 5886.6,1413.37 5953,1413.37 5968,1398.37 v1(5968,1334.37)
  ART03 w6: v1(3214.18,1356.63) 3270.81,1300 4245,1300 4345,1400 4457.52,1400 v1(4481.89,1424.37)
  BOTTOM w6: v1(4481.89,1424.37) 4520.26,1386 5120,1386 5147.63,1358.37 5944,1358.37 v1(5968,1334.37) ; v1(5910.63,1838.74) 5916.89,1845 R262.1@5990.32,1845
MIPI_CSI0_CLK0N: J1.52 J34.10 | length 6595.2
  TOP w4.5: J1.52@2065.85,465.62 2065.85,434.69 2062.72,431.57 2062.72,289.02 2080.99,270.75 2485.75,270.75 2570,355 2570,430 2618.5,478.5 2618.5,597.41 v2(2609.91,606) ; v1(6472,2058.96) 6483.33,2070.29 6496.49,2070.29 6501.59,2065.2 J34.10@6533.11,2065.2
  ART03 w4: v2(2609.91,606) 2621.73,617.82 2621.73,631.56 2636.17,646 2647.22,646 ccw(c2647.22,650.5) 2651.72,650.5 cw(c2656.22,650.5) 2656.22,655 2663.22,655 cw(c2663.22,650.5) 2667.72,650.5 ccw(c2672.22,650.5) 2672.22,646 2679.22,646 ccw(c2679.22,650.5) 2683.72,650.5 cw(c2688.22,650.5) 2688.22,655 2695.22,655 cw(c2695.22,650.5) 2699.72,650.5 ccw(c2704.22,650.5) 2704.22,646 2711.22,646 ccw(c2711.22,650.5) 2715.72,650.5 cw(c2720.22,650.5) 2720.22,655 2727.22,655 cw(c2727.22,650.5) 2731.72,650.5 ccw(c2736.22,650.5) 2736.22,646 2743.22,646 ccw(c2743.22,650.5) 2747.72,650.5 cw(c2752.22,650.5) 2752.22,655 2759.22,655 cw(c2759.22,650.5) 2763.72,650.5 ccw(c2768.22,650.5) 2768.22,646 2775.22,646 ccw(c2775.22,650.5) 2779.72,650.5 cw(c2784.22,650.5) 2784.22,655 2791.22,655 cw(c2791.22,650.5) 2795.72,650.5 ccw(c2800.22,650.5) 2800.22,646 3937.56,646 4043.56,540 4524.44,540 4600.44,616 5842,616 5870,644 5870,839.56 5896,865.56 5896,1098.44 5884,1110.44 5884,1809.93 5898.44,1824.37 6012,1824.37 6058,1870.37 6183,1870.37 6191,1878.37 6191,2025.56 6206.61,2041.17 6373.76,2041.17 6391,2023.93 6391,2003.93 6399,1995.93 6436,1995.93 6455.44,2015.37 6494.89,2015.37 6503.44,2023.93 6503.44,2061.54 6495.44,2069.54 6482.58,2069.54 v1(6472,2058.96)
MIPI_CSI0_CLK0P: J1.50 J34.9 | length 6593.5
  TOP w4.5: J1.50@2050.1,465.62 2050.1,434.69 2053.22,431.57 2053.22,285.08 2077.05,261.25 2489.69,261.25 2579.5,351.06 2579.5,426.06 2628,474.56 2628,593.41 v2(2640.59,606) ; v1(6472,2091.12) 6483.33,2079.79 6496.49,2079.79 6501.59,2084.88 J34.9@6533.11,2084.88
  ART03 w4: v2(2640.59,606) 2632.73,613.86 2632.73,627 2640.73,635 3933,635 4039,529 4529,529 4605,605 5846.56,605 5881,639.44 5881,835 5907,861 5907,1103 5895,1115 5895,1805.37 5903,1813.37 6016.56,1813.37 6062.56,1859.37 6187.56,1859.37 6202,1873.81 6202,2021 6211.17,2030.17 6369.2,2030.17 6380,2019.37 6380,1999.37 6394.44,1984.93 6440.56,1984.93 6460,2004.37 6499.44,2004.37 6514.44,2019.37 6514.44,2066.1 6500,2080.54 6482.58,2080.54 v1(6472,2091.12)
MIPI_CSI0_CLK1N: J1.36 J35.10 | length 6649.3
  TOP w4.5: J1.36@1939.86,465.62 1939.86,496.56 1936.19,500.23 1936.19,512.95 v2(1946.33,523.09)
  ART03 w4: v2(1946.33,523.09) 1936.49,513.25 1936.49,361.51 1949,349 2148,349 2156,357 2156,436.56 2170.44,451 3648,451 3663,436 3663,354 3671,346 4924,346 4968,390 5481,390 5535.63,335.37 5990.44,335.37 6025,369.93 6025,1675 6056.26,1706.26 6398.33,1706.26 6413,1720.93 6413,1816.62 6408,1821.62 6408,1832.62 6413,1837.62 6413,1848.62 6408,1853.62 6408,1864.62 6413,1869.62 6413,1880.62 6408,1885.62 6408,1896.62 6413,1901.62 6413,1912.62 6408,1917.62 6408,1928.62 6413,1933.62 6413,1944.93 6430.5,1962.43 6459.42,1962.43 v1(6470,1973.01)
  BOTTOM w4.5: v1(6470,1973.01) 6481.33,1961.68 6496.49,1961.68 6501.59,1966.77 J35.10@6533.11,1966.77
MIPI_CSI0_CLK1P: J1.34 J35.9 | length 6650.9
  TOP w4.5: v2(1915.65,523.09) 1926.69,512.05 1926.69,499.13 1924.11,496.56 J1.34@1924.11,465.62
  ART03 w4: v2(1915.65,523.09) 1925.49,513.25 1925.49,356.95 1944.44,338 2152.56,338 2167,352.44 2167,432 2175,440 3643.44,440 3652,431.44 3652,349.44 3666.44,335 4928.56,335 4972.56,379 5476.44,379 5531.07,324.37 5995,324.37 6036,365.37 6036,1670.44 6060.82,1695.26 6402.89,1695.26 6424,1716.37 6424,1940.37 6435.06,1951.43 6459.42,1951.43 v1(6470,1940.85)
  BOTTOM w4.5: v1(6470,1940.85) 6481.33,1952.18 6496.49,1952.18 6501.59,1947.09 J35.9@6533.11,1947.09
MIPI_CSI0_D0N: J1.62 J34.12 | length 6597.6
  TOP w4.5: J1.62@2144.59,465.62 2144.59,434.69 2141.46,431.57 2141.46,364.97 2168.44,338 2448,338 2490,380 2490,455 2527,492 2527,680.41 v2(2516.41,691) ; v1(6410,2019.59) 6421.33,2030.92 6496.49,2030.92 6501.59,2025.83 J34.12@6533.11,2025.83
  ART03 w4: v2(2516.41,691) 2526.83,701.42 2526.83,741.38 2544.44,759 2909,759 2929,739 3981.56,739 4023.56,697 4214.64,697 4225.77,685.87 4225.77,664.69 4230.45,660 4237.08,660 4241.77,664.69 4241.77,689.87 4252.89,701 4268.64,701 4279.77,689.87 4279.77,664.69 4284.45,660 4291.08,660 4295.77,664.69 4295.77,685.87 4306.89,697 5761.44,697 5777,712.56 5777,849.56 5812,884.56 5812,1879.56 5835.81,1903.37 5984,1903.37 6029.63,1949 6111,1949 6119,1957 6119,2143.56 6133.44,2158 6425.37,2158 6450.89,2132.48 6450.89,2044.61 6436.45,2030.17 6420.58,2030.17 v1(6410,2019.59)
